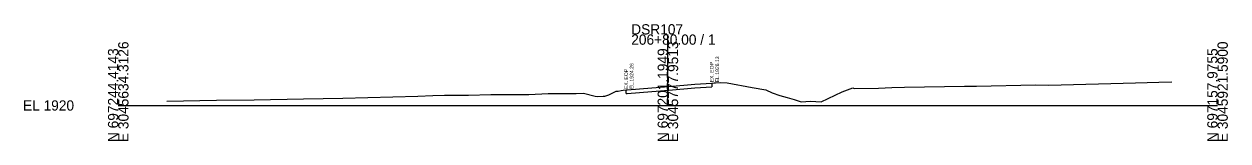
# Model space of a CAD drawing. Extents: x -26 to 19003, y -31 to 24541.
# Drawn here: x 1974.3 to 2302.8, y 15490.3 to 15522.2 of the extents above; entities that cross this region are included whole.
import ezdxf

# ---------------------------------------------------------------- set-up
doc = ezdxf.new("R2010")
doc.units = 0
for name, color, linetype in [('DESIGN - SHEET - Light Grid', 7, 'Continuous'), ('SURVEY - GROUND - Existing Pavement Layer', 7, 'Continuous'), ('SURVEY - GROUND - Existing Pavement Text', 7, 'Continuous'), ('SURVEY - GROUND - Top of Ground', 7, 'Continuous')]:
    doc.layers.add(name, color=color, linetype=linetype)

msp = doc.modelspace()

# ---------------------------------------------------------------- linework, layer by layer
at = {"layer": 'DESIGN - SHEET - Light Grid'}
for p, q in [((2150, 15500), (2150, 15519.4)), ((2000, 15500), (2150, 15500)), ((2150, 15500), (2300, 15500))]:
    msp.add_line(p, q, dxfattribs=at)
at = {"layer": 'SURVEY - GROUND - Existing Pavement Layer'}
for p, q in [((2138.6, 15503.26), (2138.6, 15504.26)), ((2138.92, 15503.3), (2145.58, 15503.83)), ((2145.58, 15503.83), (2150.28, 15504.21)), ((2150.28, 15504.21), (2157.4, 15504.78)), ((2157.4, 15504.78), (2161.98, 15505.13)), ((2161.98, 15506.13), (2161.98, 15505.13)), ((2138.6, 15503.26), (2138.92, 15503.3))]:
    msp.add_line(p, q, dxfattribs=at)
at = {"layer": 'SURVEY - GROUND - Top of Ground'}
msp.add_lwpolyline([(2013.26, 15501.16), (2026.81, 15501.44), (2037.08, 15501.52), (2050.54, 15501.8), (2061.27, 15501.99), (2081.75, 15502.57), (2085.83, 15502.7), (2089.07, 15502.79), (2090.84, 15502.84), (2095.6, 15502.84), (2101.68, 15502.98), (2103.11, 15502.99), (2105.33, 15503.01), (2112.06, 15503), (2117.35, 15503.24), (2118.27, 15503.27), (2118.6, 15503.27), (2125, 15503.28), (2127.02, 15503.36), (2130.13, 15502.5), (2130.84, 15502.42), (2132.37, 15502.55), (2132.8, 15502.58), (2133.88, 15502.94), (2135.86, 15503.87), (2136.47, 15503.94), (2137.29, 15504.09), (2137.83, 15504.15), (2138.6, 15504.26), (2138.92, 15504.3), (2145.58, 15504.83), (2150.28, 15505.21), (2157.4, 15505.78), (2161.98, 15506.13), (2162.64, 15506.18), (2162.98, 15506.21), (2164.4, 15506.24), (2166.15, 15506.19), (2173, 15504.93), (2176.71, 15504.29), (2178.48, 15503.49), (2180.58, 15502.76), (2182.52, 15502.21), (2184.43, 15501.64), (2186.42, 15501), (2188.96, 15501.14), (2191.79, 15500.98), (2197.57, 15503.77), (2200.49, 15504.82), (2200.87, 15504.61), (2207.5, 15504.7), (2211.15, 15504.91), (2214.55, 15504.98), (2230.93, 15505.23), (2234.21, 15505.26), (2250.31, 15505.6), (2253.99, 15505.59), (2277.63, 15506.21), (2284.01, 15506.39), (2287.56, 15506.47)], dxfattribs=at)

# ---------------------------------------------------------------- texts
at = {"layer": 'DESIGN - SHEET - Light Grid'}
for s, p in [('DSR107', (2140, 15519.4)), ('206+80.00 / 1', (2140, 15516.6)), ('EL 1920', (1974, 15498.6))]:
    msp.add_text(s, height=2.8, dxfattribs=at).set_placement(p)
for s, p in [('E 3045634.3126', (2002.8, 15490)), ('E 3045777.9513', (2152.8, 15490)), ('E 3045921.5900', (2302.8, 15490)), ('N 697244.4143', (2000, 15490)), ('N 697201.1949', (2150, 15490)), ('N 697157.9755', (2300, 15490))]:
    msp.add_text(s, height=2.8, rotation=90, dxfattribs=at).set_placement(p)
at = {"layer": 'SURVEY - GROUND - Existing Pavement Text'}
for s, p in [('EL.1924.26', (2140.61, 15504.46)), ('EX. EOP', (2162.48, 15506.33)), ('EL.1926.13', (2163.98, 15506.33)), ('EX. EOP', (2139.1, 15504.46))]:
    msp.add_text(s, height=1, rotation=90, dxfattribs=at).set_placement(p)

doc.saveas('drawing.dxf')
